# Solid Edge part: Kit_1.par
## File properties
Author: bmolnar
Last saved by: bmolnar
Revision: 77
Sűrűség: 0,000 kg/m^3
Pontosság: 0,990
Username: bmolnar
Dokumentum tartalom típus: 0
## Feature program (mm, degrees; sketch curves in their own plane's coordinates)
base feature "unnamed BaseFeature 1"
sketch for "Furat_1" plane through (-20.15, 0, -7.65) normal (1, 0, 0) x-axis (0, -1, 0)
  hole centre (0, -15.15) bore radius 2.067
hole "Furat_1" nominal diameter 5 finite  ThreadDepth = 5 mm; StartChamferOffset = 0.6 mm; StartChamferAngle = 45 deg
sketch for "Furat_2" plane through (-13, 13, 5.1) normal (0, 0, -1) x-axis (0, -1, 0)
  hole centre (0, 0) bore radius 2.067
hole "Furat_2" nominal diameter 5
sketch for "unnamed Hole 1" plane through (-13, 13, 5.1) normal (0, 0, -1) x-axis (0, -1, 0)
  hole centre (26, 0) bore radius 2.067
hole "unnamed Hole 1"
sketch for "unnamed Hole 2" plane through (-13, 13, 5.1) normal (0, 0, -1) x-axis (0, -1, 0)
  hole centre (26, -26) bore radius 2.067
hole "unnamed Hole 2"
sketch for "unnamed Hole 3" plane through (-13, 13, 5.1) normal (0, 0, -1) x-axis (0, -1, 0)
  hole centre (0, -26) bore radius 2.067
hole "unnamed Hole 3"
pattern "unnamed Pattern 1" of "Furat_2", "unnamed Hole 1", "unnamed Hole 2", "unnamed Hole 3"
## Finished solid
Body 1: solid body, 245 faces, 610 edges, 376 vertices, 3 internal voids.
  Faces by surface: plane 129, cylinder 52, swept 42, cone 16, torus 6
  Edges by curve: line 381, circle 135, spline 88, curve on surface 5, ellipse 1
Bounding box of the edges (mm; curved faces can reach further): 40.300 x 40.300 x 12.500, from (-20.15, -20.15, 0) to (20.15, 20.15, 12.5).
Cylindrical faces by radius (mm): R0.2 x18, R0.4246 x1, R0.4865 x1, R2.067 x5, R3.75 x2, R4 x4, R4.1 x12, R4.5 x1, R5.45 x2, R5.55 x2, R13.75 x4
Conical faces (half-angle, radius in mm at the cone's reference point): 0.5 deg R5 x4, 45 deg R2.317 x2, 45 deg R2.367 x2, 45 deg R2.667 x1, 45 deg R4.25 x2, 45 deg R4.65 x1, 45 deg R5.3 x2, 45 deg R5.35 x2
Toroidal faces (ring radius, tube radius in mm): R3.8 r0.2 x2, R4.4 r0.4 x2, R9.4957 r0.5 x1, R11.0043 r0.5 x1
Planar faces by outward normal: +x 5, +y 13, +z 4, -x 7, -y 16, -z 15, oblique 69
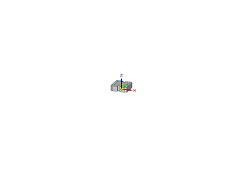
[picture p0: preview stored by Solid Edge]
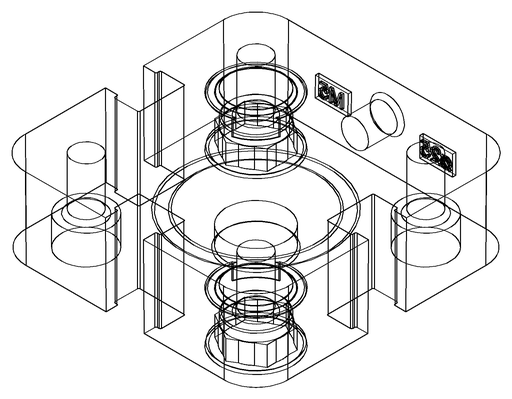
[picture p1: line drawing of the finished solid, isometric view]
